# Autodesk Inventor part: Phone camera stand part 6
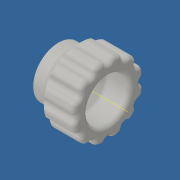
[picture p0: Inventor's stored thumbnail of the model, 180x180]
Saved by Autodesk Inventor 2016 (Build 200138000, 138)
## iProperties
Created: 2016-02
Part Number: Phone camera stand part 6
Material: Generic
Document SubType Name: Modeling
Designer: Miha
Density: 1 g/cm^3
Appearance: Default
Author: Miha
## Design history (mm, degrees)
sketch "Sketch1"
  geometry: C1 r 6 at (0, 0); 1 further point
  constraints: 1 centre point, 1 coincident
  dimensions: "d0" = 12 diameter of C1
extrude "Extrusion1" new body sketch "Sketch1" distance "d1" = 5; taper "d2" = 0 deg
sketch "Sketch2"
  geometry: C1 r 1.65 at (0, 0); 1 further point
  constraints: 1 centre point, 1 coincident
  dimensions: "d3" = 3.3 diameter of C1
extrude "Extrusion2" cut sketch "Sketch2" distance "d4" = 7; taper "d5" = 0 deg
sketch "Sketch3"
  geometry: L1 (3.349, 0)-(1.674, -2.9); L2 (1.674, -2.9)-(-1.674, -2.9); L3 (-1.674, -2.9)-(-3.349, 0); L4 (-3.349, 0)-(-1.674, 2.9); L5 (-1.674, 2.9)-(1.674, 2.9); L6 (1.674, 2.9)-(3.349, 0); C1 r 1.65 at (0, 0) reference; 1 further point
  constraints: 12 end point, 1 coincident, 13 other
  dimensions: "d10" = 2.9 distance from line of point (0, 0) L6
extrude "Extrusion3" cut sketch "Sketch3" distance "d8" = 3; taper "d9" = 0 deg
sketch "Sketch5"
  geometry: C1 r 8.5 at (0, 0); C2 r 5 at (0, 0); 1 further point
  constraints: 2 centre point, 2 coincident
  dimensions: "d11" = 17 diameter of C1; "d12" = 10 diameter of C2
extrude "Extrusion4" join sketch "Sketch5" distance "d13" = 10; taper "d14" = 0 deg
chamfer "Chamfer1" distance "d15" = 1.6; stored, may be unused: second distance "d16" = 2, angle "d17" = 45 deg
chamfer "Chamfer2" distance "d18" = 2.5; stored, may be unused: second distance "d19" = 2, angle "d20" = 45 deg
workaxis "Work Axis1"
sketch "Sketch6"
  geometry: L1 (0, -8.5)-(0, -7.104); L2 (0, -7.104)-(-1.22, -8.412); L3 (0, -7.104)-(1.22, -8.412); L4 (-3.552, -6.152)-(-5.263, -6.675); L5 (-3.552, -6.152)-(-3.149, -7.895); L6 (-6.152, -3.552)-(-7.895, -3.149); L7 (-6.152, -3.552)-(-6.675, -5.263); L8 (-7.104, 0)-(-8.412, 1.22); L9 (-7.104, 0)-(-8.412, -1.22); L10 (-6.152, 3.552)-(-6.675, 5.263); L11 (-6.152, 3.552)-(-7.895, 3.149); L12 (-3.552, 6.152)-(-3.149, 7.895); L13 (-3.552, 6.152)-(-5.263, 6.675); L14 (0, 7.104)-(1.22, 8.412); L15 (0, 7.104)-(-1.22, 8.412); L16 (3.552, 6.152)-(5.263, 6.675); L17 (3.552, 6.152)-(3.149, 7.895); L18 (6.152, 3.552)-(7.895, 3.149); L19 (6.152, 3.552)-(6.675, 5.263); L20 (7.104, 0)-(8.412, -1.22); L21 (7.104, 0)-(8.412, 1.22); L22 (6.152, -3.552)-(6.675, -5.263); L23 (6.152, -3.552)-(7.895, -3.149); L24 (3.552, -6.152)-(3.149, -7.895); L25 (3.552, -6.152)-(5.263, -6.675); A1 r 8.5 centre (0, 0) between (1.22, -8.412) and (-1.22, -8.412); A2 r 8.5 centre (0, 0) between (-3.149, -7.895) and (-5.263, -6.675); A3 r 8.5 centre (0, 0) between (-6.675, -5.263) and (-7.895, -3.149); A4 r 8.5 centre (0, 0) between (-8.412, -1.22) and (-8.412, 1.22); A5 r 8.5 centre (0, 0) between (-7.895, 3.149) and (-6.675, 5.263); A6 r 8.5 centre (0, 0) between (-5.263, 6.675) and (-3.149, 7.895); A7 r 8.5 centre (0, 0) between (-1.22, 8.412) and (1.22, 8.412); A8 r 8.5 centre (0, 0) between (3.149, 7.895) and (5.263, 6.675); A9 r 8.5 centre (0, 0) between (6.675, 5.263) and (7.895, 3.149); A10 r 8.5 centre (0, 0) between (8.412, 1.22) and (8.412, -1.22); A11 r 8.5 centre (0, 0) between (7.895, -3.149) and (6.675, -5.263); A12 r 8.5 centre (0, 0) between (5.263, -6.675) and (3.149, -7.895); 16 further points
  constraints: 50 end point, 24 point on circle, 15 coincident, 12 centre point, 1 symmetric about line, 1 vertical, 1 vertical alignment, 95 other
  dimensions: "d23" = 360 deg dimension on point (0, 0) L1.end (derived)
workaxis "Work Axis2"
extrude "Extrusion5" cut sketch "Sketch6" stored distance "d25" = 10; taper "d26" = 0 deg
fillet "Fillet1" dims "d27" = 1
fillet "Fillet3" dims "d29" = 1
sketch "Sketch8"
  geometry: C1 r 11.189 at (0, 0); 1 further point
  constraints: 1 centre point, 1 coincident
extrude "Extrusion6" cut sketch "Sketch8" distance "d31" = 3; taper "d32" = 0 deg
fillet "Fillet5" dims "d33" = 1
fillet "Fillet6" dims "d34" = 2
body "Solid1"
